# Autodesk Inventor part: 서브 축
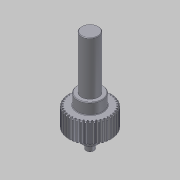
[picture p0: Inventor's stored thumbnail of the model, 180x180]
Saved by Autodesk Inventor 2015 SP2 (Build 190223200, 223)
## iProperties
Created: 2013-12
Part Number: 서브 축
Material: 강
Document SubType Name: Modeling
Designer: 한국산업디자인학원
Categories: <?xml version="1.0" encoding="UTF-16"?> <MemberInstance><Categories><FamilyTemplate><FamilyTemplateParameter ValueType="xs:double" Id="1" ObjectReferenceKey="da
Density: 1 g/cm^3
Appearance: 강철
CustomPartVersion: 1
Author: 한국산업디자인학원
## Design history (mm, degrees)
sketch "Sketch1"
  geometry: C1 r 21 at (0, 0)
  constraints: 1 centre point
  dimensions: "d0" = 42 diameter of C1 (= da_da)
extrude "Extrusion1" new body sketch "Sketch1" distance "d1" = 20 (= da_b); taper "d2" = 0 deg
workplane "Work Plane2"
feature "피치 지름" dims "d4" = 10, "d5" = 0
workplane "Work Plane8"
workplane "Work Plane9"
chamfer "모따기1" distance "d49" = 1; stored, may be unused: second distance "d50" = 2, angle "d51" = 45 deg
sketch "스케치3"
  geometry: C1 r 12.5 at (0, 0); 1 further point
  constraints: 1 centre point, 1 coincident
  dimensions: "d52" = 25 diameter of C1
extrude "돌출2" join sketch "스케치3" distance "d53" = 11; taper "d54" = 0 deg
sketch "스케치4"
  geometry: C1 r 8.5 at (0, 0); 1 further point
  constraints: 1 centre point, 1 coincident
  dimensions: "d55" = 17 diameter of C1
extrude "돌출3" join sketch "스케치4" distance "d56" = 53; taper "d57" = 0 deg
sketch "스케치5"
  geometry: C1 r 7.5 at (0, 0); 1 further point
  constraints: 1 centre point, 1 coincident
  dimensions: "d62" = 15 diameter of C1
extrude "돌출4" join sketch "스케치5" distance "d63" = 11; taper "d64" = 0 deg
sketch "스케치6"
  geometry: C1 r 4 at (0, 0); 1 further point
  constraints: 1 centre point, 1 coincident
  dimensions: "d65" = 8 diameter of C1
extrude "돌출5" join sketch "스케치6" distance "d66" = 7; taper "d67" = 0 deg
chamfer "모따기2" distance "d58" = 0.5; stored, may be unused: second distance "d59" = 2, angle "d60" = 45 deg
fillet "모깎기1" dims "d61" = 0.5
feature "스퍼 기어" dims "d34" = 4.5 deg (computed from da_z), "da_b" = 20, "da_d" = 40, "da_aw" = 31, "da_da" = 42, "da_df" = 37.5, "da_dw" = 40, angle "da_beta" = 0 deg, "da_lefttooth" = 0, "da_righttooth" = 0
body "Solid1"
sketch "Sketch2"
  geometry: C1 r 21 at (0, 0) reference; C2 r 20 at (0, 0)
  constraints: 1 centre point, 1 coincident
  dimensions: "d3" = 40 diameter of C2 (= da_dw)
body "Srf1"
other parameters: "d16" = 31 (= da_aw), "d17" = 0, "d39" = 0, "d41" = 0, "d43" = 31 (= da_aw), "d46" = 31 (= da_aw), "d47" = 0, "d48" = 0
